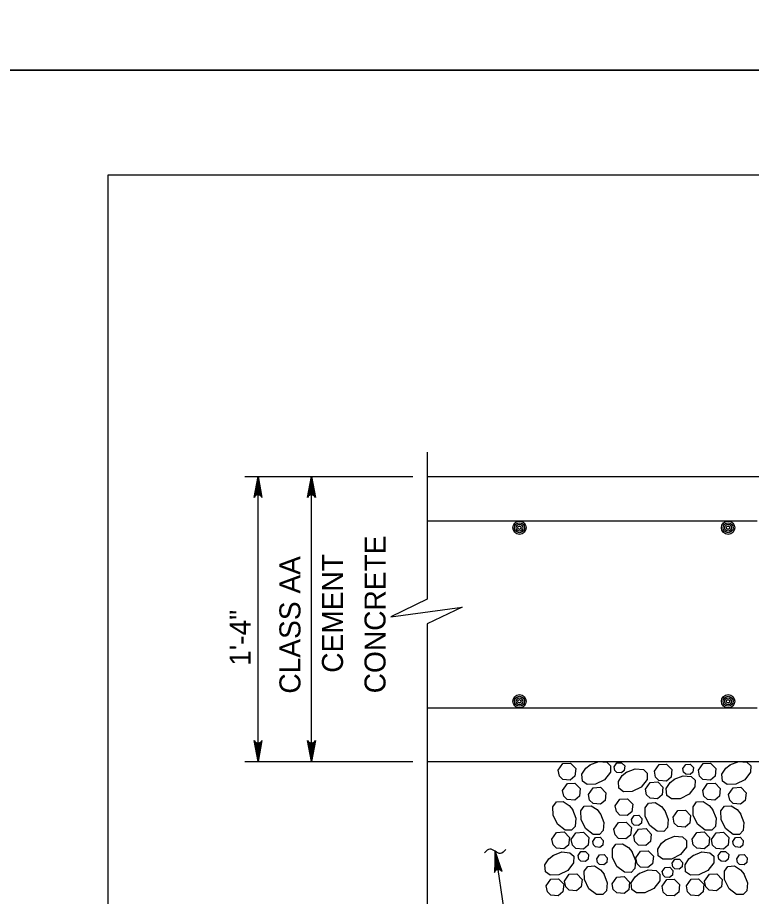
# Model space of a CAD drawing. Extents: x 636530 to 644067, y 294168 to 299122.
# Drawn here: x 639033.9 to 639138.6, y 297614.6 to 297740 of the extents above; entities that cross this region are included whole.
import ezdxf

# ---------------------------------------------------------------- set-up
doc = ezdxf.new("R2010")
doc.units = 0
doc.layers.add('1', color=7, linetype='Continuous')
doc.layers.add('PLT-BNDY', color=7, linetype='Continuous')

msp = doc.modelspace()

# ---------------------------------------------------------------- linework, layer by layer
at = {"layer": '1'}
for p, q in [((639832.78, 297717.48), (639046.78, 297717.48)), ((639046.78, 297717.48), (639046.78, 297153.48)), ((639092.35, 297678.01), (639092.35, 297657.02)), ((639066.31, 297674.51), (639090.29, 297674.51)), ((639068.21, 297633.88), (639068.21, 297674.51)), ((639075.83, 297633.88), (639075.83, 297674.51)), ((639092.35, 297674.51), (639234.69, 297674.51)), ((639092.35, 297668.17), (639139.44, 297668.17)), ((639092.35, 297653.5), (639092.35, 297609.16)), ((639092.35, 297641.5), (639139.44, 297641.5)), ((639066.31, 297633.88), (639090.29, 297633.88)), ((639092.35, 297633.88), (639234.69, 297633.88)), ((639102.05, 297621.05), (639104.52, 297604.33))]:
    msp.add_line(p, q, dxfattribs=at)
for points in [[(639068.21, 297674.51), (639068.77, 297671.53), (639068.69, 297671.65), (639068.61, 297671.76), (639068.51, 297671.82), (639068.41, 297671.88), (639068.31, 297671.9), (639068.21, 297671.91), (639068.11, 297671.9), (639068.01, 297671.88), (639067.91, 297671.82), (639067.81, 297671.76), (639067.74, 297671.65), (639067.66, 297671.53), (639068.21, 297674.51), (639067.74, 297671.65), (639067.81, 297671.76), (639068.21, 297674.51), (639067.91, 297671.82), (639068.01, 297671.88), (639068.21, 297674.51), (639068.11, 297671.9), (639068.21, 297671.91), (639068.21, 297674.51), (639068.31, 297671.9), (639068.41, 297671.88), (639068.21, 297674.51), (639068.51, 297671.82), (639068.61, 297671.76), (639068.21, 297674.51), (639068.69, 297671.65)], [(639075.83, 297674.51), (639076.39, 297671.53), (639076.31, 297671.65), (639076.23, 297671.76), (639076.13, 297671.82), (639076.03, 297671.88), (639075.93, 297671.9), (639075.83, 297671.91), (639075.73, 297671.9), (639075.63, 297671.88), (639075.53, 297671.82), (639075.43, 297671.76), (639075.36, 297671.65), (639075.28, 297671.53), (639075.83, 297674.51), (639075.36, 297671.65), (639075.43, 297671.76), (639075.83, 297674.51), (639075.53, 297671.82), (639075.63, 297671.88), (639075.83, 297674.51), (639075.73, 297671.9), (639075.83, 297671.91), (639075.83, 297674.51), (639075.93, 297671.9), (639076.03, 297671.88), (639075.83, 297674.51), (639076.13, 297671.82), (639076.23, 297671.76), (639075.83, 297674.51), (639076.31, 297671.65)], [(639092.35, 297657.02), (639087.16, 297654.48), (639097.31, 297655.86), (639092.35, 297653.5)], [(639068.21, 297633.88), (639067.66, 297636.86), (639067.74, 297636.74), (639067.81, 297636.63), (639067.91, 297636.57), (639068.01, 297636.51), (639068.11, 297636.49), (639068.21, 297636.48), (639068.31, 297636.49), (639068.41, 297636.51), (639068.51, 297636.57), (639068.61, 297636.63), (639068.69, 297636.74), (639068.77, 297636.86), (639068.21, 297633.88), (639068.69, 297636.74), (639068.61, 297636.63), (639068.21, 297633.88), (639068.51, 297636.57), (639068.41, 297636.51), (639068.21, 297633.88), (639068.31, 297636.49), (639068.21, 297636.48), (639068.21, 297633.88), (639068.11, 297636.49), (639068.01, 297636.51), (639068.21, 297633.88), (639067.91, 297636.57), (639067.81, 297636.63), (639068.21, 297633.88), (639067.74, 297636.74)], [(639075.83, 297633.88), (639075.28, 297636.86), (639075.36, 297636.74), (639075.43, 297636.63), (639075.53, 297636.57), (639075.63, 297636.51), (639075.73, 297636.49), (639075.83, 297636.48), (639075.93, 297636.49), (639076.03, 297636.51), (639076.13, 297636.57), (639076.23, 297636.63), (639076.31, 297636.74), (639076.39, 297636.86), (639075.83, 297633.88), (639076.31, 297636.74), (639076.23, 297636.63), (639075.83, 297633.88), (639076.13, 297636.57), (639076.03, 297636.51), (639075.83, 297633.88), (639075.93, 297636.49), (639075.83, 297636.48), (639075.83, 297633.88), (639075.73, 297636.49), (639075.63, 297636.51), (639075.83, 297633.88), (639075.53, 297636.57), (639075.43, 297636.63), (639075.83, 297633.88), (639075.36, 297636.74)], [(639111.04, 297632.61), (639111.71, 297633.57), (639112.79, 297633.63), (639113.53, 297632.86), (639113.42, 297631.77), (639112.76, 297631.22), (639111.7, 297631.3), (639111.2, 297631.78), (639111.04, 297632.61)], [(639116.81, 297633.88), (639117.96, 297633.78), (639118.51, 297633.25), (639118.5, 297632.32), (639117.66, 297631.25), (639116.37, 297630.61), (639115.16, 297630.59), (639114.48, 297631.07), (639114.41, 297632.04), (639114.97, 297632.9), (639115.6, 297633.41)], [(639115.55, 297633.38), (639116.81, 297633.88)], [(639119.02, 297633.08), (639119.42, 297633.66), (639120.07, 297633.69), (639120.52, 297633.23), (639120.45, 297632.58), (639120.05, 297632.25), (639119.42, 297632.29), (639119.12, 297632.58), (639119.02, 297633.08)], [(639120.76, 297632.34), (639122.02, 297632.84), (639123.18, 297632.74), (639123.72, 297632.22), (639123.71, 297631.28), (639122.87, 297630.22), (639121.59, 297629.57), (639120.37, 297629.55), (639119.69, 297630.04), (639119.62, 297631.01), (639120.18, 297631.87), (639120.81, 297632.38)], [(639124.75, 297632.47), (639125.42, 297633.42), (639126.49, 297633.49), (639127.24, 297632.71), (639127.13, 297631.63), (639126.47, 297631.08), (639125.41, 297631.15), (639124.91, 297631.64), (639124.75, 297632.47)], [(639128.82, 297632.86), (639129.23, 297633.43), (639129.87, 297633.47), (639130.32, 297633.01), (639130.26, 297632.36), (639129.86, 297632.03), (639129.22, 297632.07), (639128.92, 297632.36), (639128.83, 297632.86)], [(639131.03, 297632.61), (639131.7, 297633.57), (639132.77, 297633.63), (639133.52, 297632.86), (639133.41, 297631.77), (639132.75, 297631.22), (639131.69, 297631.3), (639131.19, 297631.78), (639131.03, 297632.61)], [(639136.8, 297633.88), (639137.95, 297633.78), (639138.5, 297633.25), (639138.48, 297632.32), (639137.65, 297631.25), (639136.36, 297630.61), (639135.15, 297630.59), (639134.47, 297631.07), (639134.4, 297632.04), (639134.96, 297632.9), (639135.59, 297633.41)], [(639135.54, 297633.38), (639136.8, 297633.88)], [(639127.6, 297631.33), (639128.85, 297631.83), (639130.01, 297631.73), (639130.56, 297631.2), (639130.54, 297630.27), (639129.71, 297629.2), (639128.42, 297628.56), (639127.2, 297628.54), (639126.52, 297629.02), (639126.46, 297629.99), (639127.01, 297630.85), (639127.65, 297631.36)], [(639111.67, 297629.75), (639112.34, 297630.71), (639113.42, 297630.77), (639114.16, 297629.99), (639114.06, 297628.91), (639113.39, 297628.36), (639112.33, 297628.43), (639111.83, 297628.92), (639111.67, 297629.75)], [(639115.35, 297629.16), (639116.02, 297630.12), (639117.09, 297630.18), (639117.84, 297629.41), (639117.73, 297628.32), (639117.07, 297627.77), (639116.01, 297627.85), (639115.51, 297628.33), (639115.35, 297629.16)], [(639123.48, 297629.94), (639124.15, 297630.89), (639125.23, 297630.96), (639125.97, 297630.18), (639125.86, 297629.1), (639125.2, 297628.55), (639124.14, 297628.62), (639123.64, 297629.11), (639123.48, 297629.94)], [(639131.66, 297629.75), (639132.33, 297630.71), (639133.41, 297630.77), (639134.15, 297629.99), (639134.04, 297628.91), (639133.38, 297628.36), (639132.32, 297628.43), (639131.82, 297628.92), (639131.66, 297629.75)], [(639135.34, 297629.16), (639136.01, 297630.12), (639137.08, 297630.18), (639137.83, 297629.41), (639137.72, 297628.32), (639137.06, 297627.77), (639136, 297627.85), (639135.5, 297628.33), (639135.34, 297629.16)], [(639113.07, 297627.03), (639113.57, 297625.77), (639113.47, 297624.61), (639112.95, 297624.06), (639112.01, 297624.08), (639110.95, 297624.91), (639110.3, 297626.2), (639110.28, 297627.42), (639110.77, 297628.1), (639111.73, 297628.16), (639112.6, 297627.61), (639113.1, 297626.97)], [(639119.17, 297627.54), (639119.84, 297628.49), (639120.92, 297628.56), (639121.66, 297627.78), (639121.55, 297626.7), (639120.89, 297626.15), (639119.83, 297626.22), (639119.33, 297626.71), (639119.17, 297627.54)], [(639126.23, 297626.86), (639126.73, 297625.61), (639126.63, 297624.45), (639126.1, 297623.9), (639125.17, 297623.92), (639124.1, 297624.75), (639123.46, 297626.04), (639123.44, 297627.25), (639123.92, 297627.94), (639124.89, 297628), (639125.75, 297627.45), (639126.26, 297626.81)], [(639133.06, 297627.03), (639133.56, 297625.77), (639133.46, 297624.61), (639132.94, 297624.06), (639132, 297624.08), (639130.93, 297624.91), (639130.29, 297626.2), (639130.27, 297627.42), (639130.75, 297628.1), (639131.72, 297628.16), (639132.59, 297627.61), (639133.09, 297626.97)], [(639117.06, 297626.42), (639117.56, 297625.16), (639117.46, 297624), (639116.93, 297623.45), (639116, 297623.47), (639114.93, 297624.3), (639114.29, 297625.59), (639114.27, 297626.81), (639114.75, 297627.49), (639115.72, 297627.55), (639116.58, 297627), (639117.09, 297626.36)], [(639127.43, 297625.91), (639128.11, 297626.87), (639129.18, 297626.93), (639129.93, 297626.16), (639129.82, 297625.07), (639129.16, 297624.52), (639128.1, 297624.6), (639127.6, 297625.08), (639127.44, 297625.91)], [(639137.05, 297626.42), (639137.54, 297625.16), (639137.44, 297624), (639136.92, 297623.45), (639135.98, 297623.47), (639134.92, 297624.3), (639134.28, 297625.59), (639134.25, 297626.81), (639134.74, 297627.49), (639135.71, 297627.55), (639136.57, 297627), (639137.08, 297626.36)], [(639118.98, 297624.22), (639119.65, 297625.17), (639120.73, 297625.23), (639121.47, 297624.46), (639121.37, 297623.38), (639120.7, 297622.83), (639119.64, 297622.9), (639119.14, 297623.39), (639118.98, 297624.22)], [(639121.48, 297625.58), (639121.88, 297626.15), (639122.53, 297626.19), (639122.97, 297625.72), (639122.91, 297625.07), (639122.51, 297624.74), (639121.88, 297624.79), (639121.58, 297625.08), (639121.48, 297625.58)], [(639121.82, 297623.27), (639122.49, 297624.22), (639123.57, 297624.29), (639124.31, 297623.51), (639124.21, 297622.43), (639123.54, 297621.88), (639122.48, 297621.95), (639121.98, 297622.44), (639121.82, 297623.27)], [(639110.14, 297622.79), (639110.81, 297623.75), (639111.88, 297623.81), (639112.63, 297623.04), (639112.52, 297621.95), (639111.86, 297621.4), (639110.8, 297621.48), (639110.3, 297621.96), (639110.14, 297622.79)], [(639112.9, 297622.75), (639113.57, 297623.71), (639114.65, 297623.77), (639115.39, 297623), (639115.29, 297621.91), (639114.62, 297621.36), (639113.56, 297621.44), (639113.06, 297621.92), (639112.9, 297622.75)], [(639115.96, 297622.46), (639116.36, 297623.03), (639117.01, 297623.07), (639117.46, 297622.6), (639117.39, 297621.95), (639116.99, 297621.62), (639116.36, 297621.67), (639116.06, 297621.96), (639115.96, 297622.46)], [(639126.38, 297622.71), (639127.63, 297623.2), (639128.79, 297623.1), (639129.34, 297622.58), (639129.32, 297621.65), (639128.49, 297620.58), (639127.2, 297619.94), (639125.98, 297619.91), (639125.3, 297620.4), (639125.24, 297621.37), (639125.79, 297622.23), (639126.43, 297622.74)], [(639130.13, 297622.79), (639130.8, 297623.75), (639131.87, 297623.81), (639132.62, 297623.04), (639132.51, 297621.95), (639131.85, 297621.4), (639130.79, 297621.48), (639130.29, 297621.96), (639130.13, 297622.79)], [(639132.89, 297622.75), (639133.56, 297623.71), (639134.64, 297623.77), (639135.38, 297623), (639135.27, 297621.91), (639134.61, 297621.36), (639133.55, 297621.44), (639133.05, 297621.92), (639132.89, 297622.75)], [(639135.95, 297622.46), (639136.35, 297623.03), (639137, 297623.07), (639137.44, 297622.6), (639137.38, 297621.95), (639136.98, 297621.62), (639136.35, 297621.67), (639136.05, 297621.96), (639135.95, 297622.46)], [(639121.55, 297621.01), (639122.05, 297619.75), (639121.95, 297618.59), (639121.43, 297618.04), (639120.49, 297618.06), (639119.42, 297618.9), (639118.78, 297620.18), (639118.76, 297621.4), (639119.24, 297622.08), (639120.21, 297622.14), (639121.08, 297621.59), (639121.58, 297620.96)], [(639102.05, 297621.05), (639101.93, 297618.02), (639101.99, 297618.15), (639102.05, 297618.27), (639102.14, 297618.35), (639102.23, 297618.42), (639102.33, 297618.45), (639102.43, 297618.48), (639102.53, 297618.48), (639102.63, 297618.48), (639102.74, 297618.43), (639102.84, 297618.39), (639102.94, 297618.29), (639103.04, 297618.19), (639102.05, 297621.05), (639102.94, 297618.29), (639102.84, 297618.39), (639102.05, 297621.05), (639102.74, 297618.43), (639102.63, 297618.48), (639102.05, 297621.05), (639102.53, 297618.48), (639102.43, 297618.48), (639102.05, 297621.05), (639102.33, 297618.45), (639102.23, 297618.42), (639102.05, 297621.05), (639102.14, 297618.35), (639102.05, 297618.27), (639102.05, 297621.05), (639101.99, 297618.15)], [(639110.29, 297620.46), (639111.55, 297620.96), (639112.7, 297620.86), (639113.25, 297620.34), (639113.23, 297619.4), (639112.4, 297618.33), (639111.11, 297617.69), (639109.9, 297617.67), (639109.21, 297618.15), (639109.15, 297619.12), (639109.7, 297619.99), (639110.34, 297620.49)], [(639113.88, 297620.44), (639114.28, 297621.01), (639114.93, 297621.05), (639115.38, 297620.59), (639115.31, 297619.94), (639114.91, 297619.6), (639114.28, 297619.65), (639113.98, 297619.94), (639113.88, 297620.44)], [(639116.53, 297619.97), (639116.93, 297620.54), (639117.58, 297620.58), (639118.02, 297620.11), (639117.96, 297619.46), (639117.56, 297619.13), (639116.93, 297619.18), (639116.63, 297619.47), (639116.53, 297619.97)], [(639122.12, 297620.12), (639122.79, 297621.08), (639123.87, 297621.14), (639124.61, 297620.37), (639124.51, 297619.28), (639123.84, 297618.73), (639122.78, 297618.81), (639122.28, 297619.29), (639122.12, 297620.12)], [(639130.28, 297620.46), (639131.53, 297620.96), (639132.69, 297620.86), (639133.24, 297620.34), (639133.22, 297619.4), (639132.39, 297618.33), (639131.1, 297617.69), (639129.89, 297617.67), (639129.2, 297618.15), (639129.14, 297619.12), (639129.69, 297619.99), (639130.33, 297620.49)], [(639133.87, 297620.44), (639134.27, 297621.01), (639134.92, 297621.05), (639135.36, 297620.59), (639135.3, 297619.94), (639134.9, 297619.6), (639134.27, 297619.65), (639133.97, 297619.94), (639133.87, 297620.44)], [(639136.52, 297619.97), (639136.92, 297620.54), (639137.56, 297620.58), (639138.01, 297620.11), (639137.95, 297619.46), (639137.55, 297619.13), (639136.91, 297619.18), (639136.61, 297619.47), (639136.52, 297619.97)], [(639117.54, 297617.83), (639118.04, 297616.58), (639117.94, 297615.42), (639117.42, 297614.87), (639116.48, 297614.89), (639115.42, 297615.72), (639114.77, 297617.01), (639114.75, 297618.22), (639115.24, 297618.91), (639116.21, 297618.97), (639117.07, 297618.42), (639117.58, 297617.78)], [(639127.28, 297619.34), (639127.68, 297619.91), (639128.33, 297619.95), (639128.78, 297619.48), (639128.71, 297618.83), (639128.31, 297618.5), (639127.68, 297618.55), (639127.38, 297618.84), (639127.28, 297619.34)], [(639137.53, 297617.83), (639138.03, 297616.58), (639137.93, 297615.42), (639137.41, 297614.87), (639136.47, 297614.89), (639135.41, 297615.72), (639134.76, 297617.01), (639134.74, 297618.22), (639135.23, 297618.91), (639136.19, 297618.97), (639137.06, 297618.42), (639137.57, 297617.78)], [(639111.94, 297616.81), (639112.61, 297617.77), (639113.68, 297617.83), (639114.43, 297617.05), (639114.32, 297615.97), (639113.66, 297615.42), (639112.6, 297615.49), (639112.1, 297615.98), (639111.94, 297616.81)], [(639122.59, 297617.9), (639123.85, 297618.4), (639125, 297618.3), (639125.55, 297617.77), (639125.54, 297616.84), (639124.7, 297615.77), (639123.41, 297615.13), (639122.2, 297615.11), (639121.52, 297615.59), (639121.45, 297616.56), (639122.01, 297617.42), (639122.64, 297617.93)], [(639125.89, 297618.17), (639126.3, 297618.74), (639126.94, 297618.78), (639127.39, 297618.32), (639127.32, 297617.67), (639126.93, 297617.34), (639126.29, 297617.38), (639125.99, 297617.67), (639125.89, 297618.17)], [(639131.92, 297616.81), (639132.6, 297617.77), (639133.67, 297617.83), (639134.42, 297617.05), (639134.31, 297615.97), (639133.64, 297615.42), (639132.59, 297615.49), (639132.09, 297615.98), (639131.92, 297616.81)], [(639109.33, 297616.11), (639110, 297617.06), (639111.07, 297617.13), (639111.82, 297616.35), (639111.71, 297615.27), (639111.05, 297614.72), (639109.99, 297614.79), (639109.49, 297615.28), (639109.33, 297616.11)], [(639118.71, 297616.42), (639119.39, 297617.38), (639120.46, 297617.44), (639121.21, 297616.67), (639121.1, 297615.58), (639120.44, 297615.03), (639119.38, 297615.11), (639118.88, 297615.59), (639118.72, 297616.42)], [(639125.85, 297616.07), (639126.52, 297617.02), (639127.59, 297617.09), (639128.34, 297616.31), (639128.23, 297615.23), (639127.57, 297614.68), (639126.51, 297614.75), (639126.01, 297615.24), (639125.85, 297616.07)], [(639129.32, 297616.11), (639129.99, 297617.06), (639131.06, 297617.13), (639131.81, 297616.35), (639131.7, 297615.27), (639131.04, 297614.72), (639129.98, 297614.79), (639129.48, 297615.28), (639129.32, 297616.11)]]:
    msp.add_lwpolyline(points, dxfattribs=at)
for centre, radius in [((639105.51, 297667.21), 0.952), ((639105.51, 297667.21), 0.714), ((639135.27, 297667.21), 0.952), ((639135.27, 297667.21), 0.714), ((639105.51, 297667.21), 0.476), ((639105.51, 297667.21), 0.238), ((639135.27, 297667.21), 0.476), ((639135.27, 297667.21), 0.238), ((639105.51, 297642.45), 0.952), ((639105.51, 297642.45), 0.714), ((639105.51, 297642.45), 0.476), ((639105.51, 297642.45), 0.238), ((639135.27, 297642.45), 0.952), ((639135.27, 297642.45), 0.714), ((639135.27, 297642.45), 0.476), ((639135.27, 297642.45), 0.238)]:
    msp.add_circle(centre, radius, dxfattribs=at)
msp.add_spline([(639103.58, 297621.31), (639102.8, 297620.73), (639101.29, 297621.38), (639100.5, 297620.85)], degree=3, dxfattribs=at)
at = {"layer": 'PLT-BNDY'}
for points in [[(639006.78, 298326.48), (639847.78, 298326.48), (639847.78, 297732.48), (639006.78, 297732.48)], [(639006.78, 297732.48), (639847.78, 297732.48), (639847.78, 297138.48), (639006.78, 297138.48)]]:
    msp.add_lwpolyline(points, close=True, dxfattribs=at)

# ---------------------------------------------------------------- texts
at = {"layer": '1'}
for s, p in [('CONCRETE', (639086.4, 297643.59)), ('CLASS AA', (639074.26, 297643.54)), ('CEMENT', (639080.33, 297646.52)), ('1\'-4"', (639067.15, 297647.51))]:
    msp.add_text(s, height=3, rotation=90, dxfattribs=at).set_placement(p)

doc.saveas('drawing.dxf')
